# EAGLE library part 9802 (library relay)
Surface Mount Reed Relays Source: COTO TECHNOLOGY - 9852-03-00 - RELAY - 91349.pdf
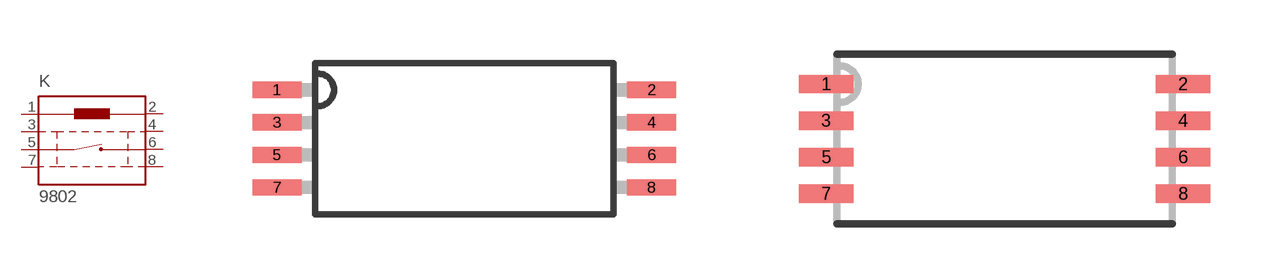
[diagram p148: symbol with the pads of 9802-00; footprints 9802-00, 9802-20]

Designator prefix K

## 9802-03-00 (OC_FARNELL: unknown; OC_NEWARK: unknown), 9802-05-00 (MF: COTO TECHNOLOGY; MPN: 9802-05-00; OC_FARNELL: 1081689; OC_NEWARK: 16F3689)  [9802-00]
1  1  pas
2  2  pas
3  3  pas
4  4  pas
5  5  pas
6  6  pas
7  7  pas
8  8  pas

## 9802-03-20 (OC_FARNELL: unknown; OC_NEWARK: unknown), 9802-05-20 (MF: COTO TECHNOLOGY; MPN: 9802-05-20; OC_FARNELL: 1081633; OC_NEWARK: 92F3367)  [9802-20]
Pads as for 9802-00

## Footprint 9802-00 (pad centres in mm)
Surface Mount Reed Relays Gull Wing Source: COTO TECHNOLOGY - 9852-03-00 - RELAY - 91349.pdf
smd 1.524 x 0.508: 1 -5.842,1.524; 2 5.842,1.524; 3 -5.842,0.508; 4 5.842,0.508; 5 -5.842,-0.508; 6 5.842,-0.508; 7 -5.842,-1.524; 8 5.842,-1.524

## Footprint 9802-20 (pad centres in mm)
Surface Mount Reed Relays J-Lead Source: COTO TECHNOLOGY - 9852-03-00 - RELAY - 91349.pdf
smd 1.524 x 0.508: 1 -4.953,1.524; 2 4.953,1.524; 3 -4.953,0.508; 4 4.953,0.508; 5 -4.953,-0.508; 6 4.953,-0.508; 7 -4.953,-1.524; 8 4.953,-1.524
